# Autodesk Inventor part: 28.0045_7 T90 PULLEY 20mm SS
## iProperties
Created: 2006-12
Document SubType Name: Modeling
Designer: Andy Moles
Part Number: 28.0045_7 T90 PULLEY 20mm SS
Material: Aluminum-6061
Density: 2.71 g/cm^3
Author: Andy Moles
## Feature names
1. Extrusion1
2. Extrusion3
3. Extrusion4
4. Extrusion6
5. Mirror1
6. Extrusion7
7. Chamfer1
